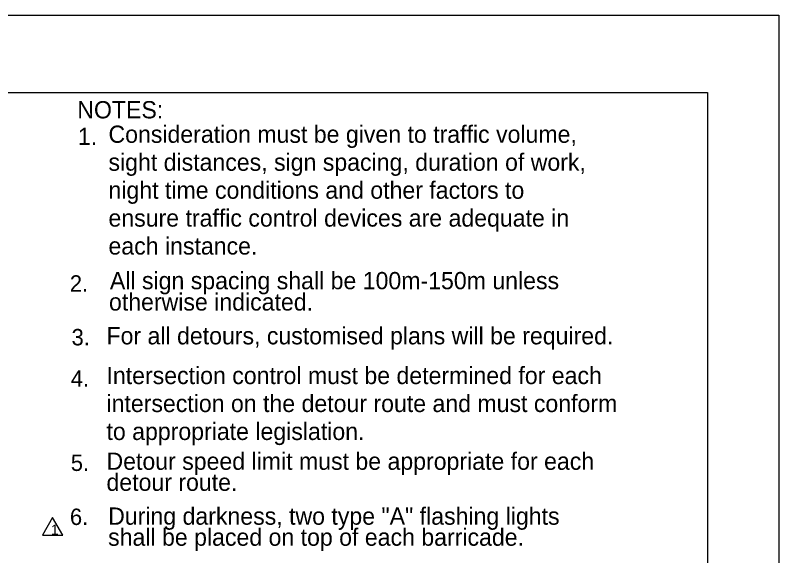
# Model space of a CAD drawing. Extents: x 1806 to 2022, y 110 to 389.
# Drawn here: x 1914.6 to 2021.6, y 313.4 to 389.2 of the extents above; entities that cross this region are included whole.
import ezdxf

# ---------------------------------------------------------------- set-up
doc = ezdxf.new("R2010")
doc.units = 0
for name, color, linetype in [('Level 10', 7, 'Continuous'), ('Level 44', 7, 'Continuous'), ('Level 60', 7, 'Continuous')]:
    doc.layers.add(name, color=color, linetype=linetype)

msp = doc.modelspace()

# ---------------------------------------------------------------- linework, layer by layer
at = {"layer": 'Level 44'}
msp.add_lwpolyline([(1919.85, 318.73), (1918.43, 316.26), (1921.27, 316.26)], close=True, dxfattribs=at)
at = {"layer": 'Level 60'}
for points in [[(1805.59, 389.18), (2021.59, 389.18), (2021.59, 110.18), (1805.59, 110.18)], [(1824.71, 378.37), (2011.59, 378.37), (2011.59, 120.99), (1824.71, 120.99)]]:
    msp.add_lwpolyline(points, close=True, dxfattribs=at)

# ---------------------------------------------------------------- texts
at = {"layer": 'Level 10'}
for s, height, p in [('NOTES:', 2.419, (1923.31, 374.72)), ('1.', 2.419, (1923.4, 370.99)), ('Consideration must be given to traffic volume,', 2.419, (1927.68, 371.29)), ('sight distances, sign spacing, duration of work,', 2.419, (1927.68, 367.37)), ('night time conditions and other factors to', 2.419, (1927.68, 363.45)), ('ensure traffic control devices are adequate in', 2.419, (1927.68, 359.54)), ('each instance.', 2.419, (1927.68, 355.62)), ('All sign spacing shall be 100m-150m unless', 2.419, (1927.88, 350.76)), ('2.', 2.299, (1922.27, 350.42)), ('otherwise indicated.', 2.419, (1927.75, 347.77)), ('For all detours, customised plans will be required.', 2.419, (1927.4, 343.03)), ('3. ', 2.299, (1922.51, 342.89)), ('4. ', 2.299, (1922.4, 337.1)), ('Intersection control must be determined for each ', 2.419, (1927.4, 337.46)), ('intersection on the detour route and must conform ', 2.419, (1927.4, 333.54)), ('to appropriate legislation.', 2.419, (1927.4, 329.62)), ('5.', 2.299, (1922.4, 325.28)), ('Detour speed limit must be appropriate for each ', 2.419, (1927.4, 325.44)), ('detour route.', 2.419, (1927.4, 322.49)), ('6.', 2.299, (1922.28, 317.7)), ('During darkness, two type "A" flashing lights', 2.419, (1927.63, 317.74)), ('shall be placed on top of each barricade.', 2.419, (1927.63, 314.79))]:
    msp.add_text(s, height=height, dxfattribs=at).set_placement(p)
at = {"layer": 'Level 44'}
msp.add_text('1', height=1.45, rotation=360, dxfattribs=at).set_placement((1919.62, 316.31))

doc.saveas('drawing.dxf')
